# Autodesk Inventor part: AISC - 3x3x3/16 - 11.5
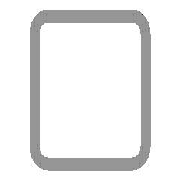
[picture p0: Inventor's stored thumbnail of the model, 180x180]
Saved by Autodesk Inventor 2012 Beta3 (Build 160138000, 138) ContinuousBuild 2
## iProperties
_CCFamilyMember: 9
_CCFamilyDisplayName: ANSI AISC (Square) - Tube
_FrameMemberDoc: Frame Member File
_Version: 15.0.0
_GetPNFromCC: 1
Created: 2010-11
Part Number: AISC - 3x3x3/16 - 11.5
Material: Steel, Mild
Description: Tube
Document SubType Name: Modeling
Standard: ANSI
Designer: Beta-8540w
Standards Organization: ANSI
Language: en-US
Size Designation: 3x3x3/16
Categories: <MemberInstance><Categories><Category DisplayName="Structural Shapes" InternalName="089c4875-fa83-4c05-b084-43b9cc11f5ed" Mnemonic="GRDR"><CategoryParameter Dis
Stock Number: 3x3x3/16
Density: 7.86 g/cm^3
IsCustomPart: 1
G_L: 11.500 in
G_W: 3.000 in
G_H: 3.000 in
Author: Beta-8540w
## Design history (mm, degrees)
node "Start plane"
node "End plane"
sketch "Sketch"
  geometry: L1 (-38.1, -28.575)-(-38.1, 28.575); L2 (-28.575, 38.1)-(28.575, 38.1); L3 (38.1, 28.575)-(38.1, -28.575); L4 (28.575, -38.1)-(-28.575, -38.1); L5 (-28.575, 33.337)-(28.575, 33.338); L6 (33.338, 28.575)-(33.338, -28.575); L7 (28.575, -33.337)-(-28.575, -33.338); L8 (-33.338, -28.575)-(-33.338, 28.575); L9 (0, 56.102)-(0, -56.102) reference; L10 (-56.102, 0)-(56.102, 0) reference; A1 r 9.525 centre (-28.575, -28.575) between (-38.1, -28.575) and (-28.575, -38.1); A2 r 9.525 centre (-28.575, 28.575) between (-28.575, 38.1) and (-38.1, 28.575); A3 r 9.525 centre (28.575, 28.575) between (38.1, 28.575) and (28.575, 38.1); A4 r 9.525 centre (28.575, -28.575) between (28.575, -38.1) and (38.1, -28.575); A5 r 4.763 centre (-28.575, 28.575) between (-28.575, 33.337) and (-33.338, 28.575); A6 r 4.763 centre (28.575, 28.575) between (33.338, 28.575) and (28.575, 33.338); A7 r 4.763 centre (28.575, -28.575) between (28.575, -33.337) and (33.338, -28.575); A8 r 4.763 centre (-28.575, -28.575) between (-33.338, -28.575) and (-28.575, -33.338)
  constraints: 16 end point, 16 point on circle, 8 centre point, 8 tangent, 4 parallel, 3 equal radius, 2 perpendicular, 7 other
  dimensions: "d10" = 76.2 distance between parallel lines of L2 L4 (= G_H); "d11" = 76.2 distance between parallel lines of L1 L3 (= G_W); "d12" = 4.7625 distance between parallel lines of L3 L6 (= G_T); "d15" = 38.1 distance between parallel lines of L2 L10 (= 0.5 x d10); "d16" = 38.1 distance between parallel lines of L9 L3 (= 0.5 x d11); "d17" = 9.525 radius of A1 (= G_IR)
extrude "Body" new body sketch "Sketch" stored distance "d3" = 292.1 (= G_L); taper "d4" = 0 deg
node "Driven Length"
  sketch "Sketch3"
    geometry: L1 (0, 0)-(10, 0) reference
    constraints: 2 end point, 1 horizontal
  workplane "Work Plane3"
  sketch "Sketch4"
    geometry: L1 (-2, 0)-(12, 0) reference; L2 (-2, 292.1)-(12, 292.1) reference
    dimensions: "d19" = 292.1 distance between parallel lines of L1 L2 (derived)
workplane "Work Plane4"
split "Split1"
body "Solid1"
other parameters: "G_W" = 76.2 [user parameter; used in 1 equation term], "G_H" = 76.2 [user parameter; used in 1 equation term], "G_T" = 4.7625 [user parameter; used in 1 equation term], "G_IR" = 9.525 [user parameter; used in 1 equation term], "G_L" = 292.1 (= d19) [user parameter; used in 1 equation term], "G_OFFSET_START" = 0 [user parameter; used in 1 equation term], "G_OFFSET_END" = 38.1 [user parameter; used in 1 equation term], "d13" = 0 (computed from G_OFFSET_START), "d14" = 292.1 (= G_OFFSET_END + B_L), "B_L" = 254 [user parameter; used in 1 equation term], "d18" = 90 deg
